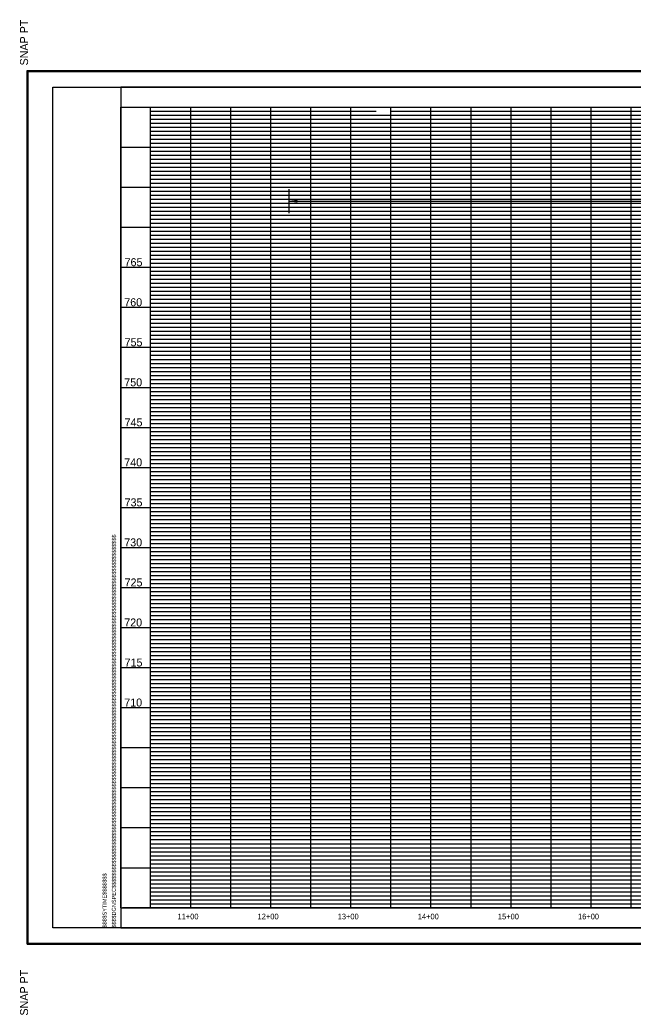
# Model space of a CAD drawing. Extents: x -273 to 1681765, y -325 to 521384.
# Drawn here: x 1680054 to 1680819, y 520141 to 521384 of the extents above; entities that cross this region are included whole.
import ezdxf

# ---------------------------------------------------------------- set-up
doc = ezdxf.new("R2010")
doc.units = 0
for name, color, linetype in [('DESIGN - PROFILE - Proposed Text', 7, 'Continuous'), ('DESIGN - SHEET - Corner Text', 7, 'Continuous'), ('DESIGN - SHEET - Light Grid', 7, 'Continuous'), ('DESIGN - SHEET - Linework', 7, 'Continuous'), ('DESIGN - SHEET - Plot Shape', 7, 'Continuous')]:
    doc.layers.add(name, color=color, linetype=linetype)

msp = doc.modelspace()

# ---------------------------------------------------------------- linework, layer by layer
at = {"layer": 'DESIGN - PROFILE - Proposed Text'}
for p, q in [((1680389.9, 521142.3), (1680389.9, 521172.3)), ((1680389.9, 521157.3), (1681439.9, 521157.3)), ((1680180, 520249.8), (1680180, 520249.8))]:
    msp.add_line(p, q, dxfattribs=at)
msp.add_lwpolyline([(1680389.9, 521157.3), (1680400, 521158.6), (1680398.7, 521157.3), (1680400, 521156)], close=True, dxfattribs=at)
msp.add_lwpolyline([(1680389.9, 521157.3), (1680400, 521158.6), (1680398.7, 521157.3), (1680400, 521156), (1680389.9, 521157.3)], dxfattribs=at)
at = {"layer": 'DESIGN - SHEET - Light Grid'}
for p, q in [((1680217.1, 521269.8), (1680498.7, 521269.8)), ((1680217.1, 521264.8), (1680517.1, 521264.8)), ((1680217.1, 521259.8), (1680517.1, 521259.8)), ((1680517.1, 521269.8), (1680867.1, 521269.8)), ((1680517.1, 521264.8), (1680867.1, 521264.8)), ((1680517.1, 521259.8), (1680867.1, 521259.8)), ((1680217.1, 521254.8), (1680517.1, 521254.8)), ((1680217.1, 521249.8), (1680517.1, 521249.8)), ((1680517.1, 521254.8), (1680867.1, 521254.8)), ((1680517.1, 521249.8), (1680867.1, 521249.8)), ((1680217.1, 521244.8), (1680517.1, 521244.8)), ((1680217.1, 521239.8), (1680517.1, 521239.8)), ((1680217.1, 521234.8), (1680517.1, 521234.8)), ((1680517.1, 521244.8), (1680867.1, 521244.8)), ((1680517.1, 521239.8), (1680867.1, 521239.8)), ((1680517.1, 521234.8), (1680867.1, 521234.8)), ((1680217.1, 521229.8), (1680517.1, 521229.8)), ((1680517.1, 521229.8), (1680867.1, 521229.8)), ((1680217.1, 521219.8), (1680517.1, 521219.8)), ((1680217.1, 521214.8), (1680517.1, 521214.8)), ((1680217.1, 521209.8), (1680517.1, 521209.8)), ((1680517.1, 521219.8), (1680867.1, 521219.8)), ((1680517.1, 521214.8), (1680867.1, 521214.8)), ((1680517.1, 521209.8), (1680867.1, 521209.8)), ((1680217.1, 521204.8), (1680517.1, 521204.8)), ((1680217.1, 521199.8), (1680517.1, 521199.8)), ((1680517.1, 521204.8), (1680867.1, 521204.8)), ((1680517.1, 521199.8), (1680867.1, 521199.8)), ((1680217.1, 521194.8), (1680517.1, 521194.8)), ((1680217.1, 521189.8), (1680517.1, 521189.8)), ((1680217.1, 521184.8), (1680517.1, 521184.8)), ((1680517.1, 521194.8), (1680867.1, 521194.8)), ((1680517.1, 521189.8), (1680867.1, 521189.8)), ((1680517.1, 521184.8), (1680867.1, 521184.8)), ((1680217.1, 521179.8), (1680517.1, 521179.8)), ((1680517.1, 521179.8), (1680867.1, 521179.8)), ((1680217.1, 521169.8), (1680517.1, 521169.8)), ((1680217.1, 521164.8), (1680517.1, 521164.8)), ((1680217.1, 521159.8), (1680517.1, 521159.8)), ((1680517.1, 521169.8), (1680867.1, 521169.8)), ((1680517.1, 521164.8), (1680867.1, 521164.8)), ((1680517.1, 521159.8), (1680867.1, 521159.8)), ((1680217.1, 521154.8), (1680517.1, 521154.8)), ((1680217.1, 521149.8), (1680517.1, 521149.8)), ((1680517.1, 521154.8), (1680867.1, 521154.8)), ((1680517.1, 521149.8), (1680867.1, 521149.8)), ((1680217.1, 521144.8), (1680517.1, 521144.8)), ((1680217.1, 521139.8), (1680517.1, 521139.8)), ((1680217.1, 521134.8), (1680517.1, 521134.8)), ((1680517.1, 521144.8), (1680867.1, 521144.8)), ((1680517.1, 521139.8), (1680867.1, 521139.8)), ((1680517.1, 521134.8), (1680867.1, 521134.8)), ((1680217.1, 521129.8), (1680517.1, 521129.8)), ((1680517.1, 521129.8), (1680867.1, 521129.8)), ((1680217.1, 521119.8), (1680517.1, 521119.8)), ((1680217.1, 521114.8), (1680517.1, 521114.8)), ((1680217.1, 521109.8), (1680517.1, 521109.8)), ((1680517.1, 521119.8), (1680867.1, 521119.8)), ((1680517.1, 521114.8), (1680867.1, 521114.8)), ((1680517.1, 521109.8), (1680867.1, 521109.8)), ((1680217.1, 521104.8), (1680517.1, 521104.8)), ((1680217.1, 521099.8), (1680517.1, 521099.8)), ((1680517.1, 521104.8), (1680867.1, 521104.8)), ((1680517.1, 521099.8), (1680867.1, 521099.8)), ((1680217.1, 521094.8), (1680517.1, 521094.8)), ((1680217.1, 521089.8), (1680517.1, 521089.8)), ((1680217.1, 521084.8), (1680517.1, 521084.8)), ((1680517.1, 521094.8), (1680867.1, 521094.8)), ((1680517.1, 521089.8), (1680867.1, 521089.8)), ((1680517.1, 521084.8), (1680867.1, 521084.8)), ((1680217.1, 521079.8), (1680517.1, 521079.8)), ((1680517.1, 521079.8), (1680867.1, 521079.8)), ((1680217.1, 521069.8), (1680517.1, 521069.8)), ((1680217.1, 521064.8), (1680517.1, 521064.8)), ((1680217.1, 521059.8), (1680517.1, 521059.8)), ((1680517.1, 521069.8), (1680867.1, 521069.8)), ((1680517.1, 521064.8), (1680867.1, 521064.8)), ((1680517.1, 521059.8), (1680867.1, 521059.8)), ((1680217.1, 521054.8), (1680517.1, 521054.8)), ((1680217.1, 521049.8), (1680517.1, 521049.8)), ((1680517.1, 521054.8), (1680867.1, 521054.8)), ((1680517.1, 521049.8), (1680867.1, 521049.8)), ((1680217.1, 521044.8), (1680517.1, 521044.8)), ((1680217.1, 521039.8), (1680517.1, 521039.8)), ((1680217.1, 521034.8), (1680517.1, 521034.8)), ((1680517.1, 521044.8), (1680867.1, 521044.8)), ((1680517.1, 521039.8), (1680867.1, 521039.8)), ((1680517.1, 521034.8), (1680867.1, 521034.8)), ((1680217.1, 521029.8), (1680517.1, 521029.8)), ((1680517.1, 521029.8), (1680867.1, 521029.8)), ((1680217.1, 521019.8), (1680517.1, 521019.8)), ((1680217.1, 521014.8), (1680517.1, 521014.8)), ((1680217.1, 521009.8), (1680517.1, 521009.8)), ((1680517.1, 521019.8), (1680867.1, 521019.8)), ((1680517.1, 521014.8), (1680867.1, 521014.8)), ((1680517.1, 521009.8), (1680867.1, 521009.8)), ((1680217.1, 521004.8), (1680517.1, 521004.8)), ((1680217.1, 520999.8), (1680517.1, 520999.8)), ((1680517.1, 521004.8), (1680867.1, 521004.8)), ((1680517.1, 520999.8), (1680867.1, 520999.8)), ((1680217.1, 520994.8), (1680517.1, 520994.8)), ((1680217.1, 520989.8), (1680517.1, 520989.8)), ((1680217.1, 520984.8), (1680517.1, 520984.8)), ((1680517.1, 520994.8), (1680867.1, 520994.8)), ((1680517.1, 520989.8), (1680867.1, 520989.8)), ((1680517.1, 520984.8), (1680867.1, 520984.8)), ((1680217.1, 520979.8), (1680517.1, 520979.8)), ((1680517.1, 520979.8), (1680867.1, 520979.8)), ((1680217.1, 520969.8), (1680517.1, 520969.8)), ((1680217.1, 520964.8), (1680517.1, 520964.8)), ((1680217.1, 520959.8), (1680517.1, 520959.8)), ((1680517.1, 520969.8), (1680867.1, 520969.8)), ((1680517.1, 520964.8), (1680867.1, 520964.8)), ((1680517.1, 520959.8), (1680867.1, 520959.8)), ((1680217.1, 520954.8), (1680517.1, 520954.8)), ((1680217.1, 520949.8), (1680517.1, 520949.8)), ((1680517.1, 520954.8), (1680867.1, 520954.8)), ((1680517.1, 520949.8), (1680867.1, 520949.8)), ((1680217.1, 520944.8), (1680517.1, 520944.8)), ((1680217.1, 520939.8), (1680517.1, 520939.8)), ((1680217.1, 520934.8), (1680517.1, 520934.8)), ((1680517.1, 520944.8), (1680867.1, 520944.8)), ((1680517.1, 520939.8), (1680867.1, 520939.8)), ((1680517.1, 520934.8), (1680867.1, 520934.8)), ((1680217.1, 520929.8), (1680517.1, 520929.8)), ((1680517.1, 520929.8), (1680867.1, 520929.8)), ((1680217.1, 520919.8), (1680517.1, 520919.8)), ((1680217.1, 520914.8), (1680517.1, 520914.8)), ((1680517.1, 520919.8), (1680867.1, 520919.8)), ((1680517.1, 520914.8), (1680867.1, 520914.8)), ((1680217.1, 520909.8), (1680517.1, 520909.8)), ((1680217.1, 520904.8), (1680517.1, 520904.8)), ((1680217.1, 520899.8), (1680517.1, 520899.8)), ((1680517.1, 520909.8), (1680867.1, 520909.8)), ((1680517.1, 520904.8), (1680867.1, 520904.8)), ((1680517.1, 520899.8), (1680867.1, 520899.8)), ((1680217.1, 520894.8), (1680517.1, 520894.8)), ((1680217.1, 520889.8), (1680517.1, 520889.8)), ((1680517.1, 520894.8), (1680867.1, 520894.8)), ((1680517.1, 520889.8), (1680867.1, 520889.8)), ((1680217.1, 520884.8), (1680517.1, 520884.8)), ((1680217.1, 520879.8), (1680517.1, 520879.8)), ((1680517.1, 520884.8), (1680867.1, 520884.8)), ((1680517.1, 520879.8), (1680867.1, 520879.8)), ((1680217.1, 520869.8), (1680517.1, 520869.8)), ((1680217.1, 520864.8), (1680517.1, 520864.8)), ((1680517.1, 520869.8), (1680867.1, 520869.8)), ((1680517.1, 520864.8), (1680867.1, 520864.8)), ((1680217.1, 520859.8), (1680517.1, 520859.8)), ((1680217.1, 520854.8), (1680517.1, 520854.8)), ((1680217.1, 520849.8), (1680517.1, 520849.8)), ((1680517.1, 520859.8), (1680867.1, 520859.8)), ((1680517.1, 520854.8), (1680867.1, 520854.8)), ((1680517.1, 520849.8), (1680867.1, 520849.8)), ((1680217.1, 520844.8), (1680517.1, 520844.8)), ((1680217.1, 520839.8), (1680517.1, 520839.8)), ((1680517.1, 520844.8), (1680867.1, 520844.8)), ((1680517.1, 520839.8), (1680867.1, 520839.8)), ((1680217.1, 520834.8), (1680517.1, 520834.8)), ((1680217.1, 520829.8), (1680517.1, 520829.8)), ((1680517.1, 520834.8), (1680867.1, 520834.8)), ((1680517.1, 520829.8), (1680867.1, 520829.8)), ((1680217.1, 520819.8), (1680517.1, 520819.8)), ((1680217.1, 520814.8), (1680517.1, 520814.8)), ((1680517.1, 520819.8), (1680867.1, 520819.8)), ((1680517.1, 520814.8), (1680867.1, 520814.8)), ((1680217.1, 520809.8), (1680517.1, 520809.8)), ((1680217.1, 520804.8), (1680517.1, 520804.8)), ((1680217.1, 520799.8), (1680517.1, 520799.8)), ((1680517.1, 520809.8), (1680867.1, 520809.8)), ((1680517.1, 520804.8), (1680867.1, 520804.8)), ((1680517.1, 520799.8), (1680867.1, 520799.8)), ((1680217.1, 520794.8), (1680517.1, 520794.8)), ((1680217.1, 520789.8), (1680517.1, 520789.8)), ((1680517.1, 520794.8), (1680867.1, 520794.8)), ((1680517.1, 520789.8), (1680867.1, 520789.8)), ((1680217.1, 520784.8), (1680517.1, 520784.8)), ((1680217.1, 520779.8), (1680517.1, 520779.8)), ((1680517.1, 520784.8), (1680867.1, 520784.8)), ((1680517.1, 520779.8), (1680867.1, 520779.8)), ((1680217.1, 520769.8), (1680517.1, 520769.8)), ((1680217.1, 520764.8), (1680517.1, 520764.8)), ((1680517.1, 520769.8), (1680867.1, 520769.8)), ((1680517.1, 520764.8), (1680867.1, 520764.8)), ((1680217.1, 520759.8), (1680517.1, 520759.8)), ((1680217.1, 520754.8), (1680517.1, 520754.8)), ((1680217.1, 520749.8), (1680517.1, 520749.8)), ((1680517.1, 520759.8), (1680867.1, 520759.8)), ((1680517.1, 520754.8), (1680867.1, 520754.8)), ((1680517.1, 520749.8), (1680867.1, 520749.8)), ((1680217.1, 520744.8), (1680517.1, 520744.8)), ((1680217.1, 520739.8), (1680517.1, 520739.8)), ((1680517.1, 520744.8), (1680867.1, 520744.8)), ((1680517.1, 520739.8), (1680867.1, 520739.8)), ((1680217.1, 520734.8), (1680517.1, 520734.8)), ((1680217.1, 520729.8), (1680517.1, 520729.8)), ((1680517.1, 520734.8), (1680867.1, 520734.8)), ((1680517.1, 520729.8), (1680867.1, 520729.8)), ((1680217.1, 520719.8), (1680517.1, 520719.8)), ((1680217.1, 520714.8), (1680517.1, 520714.8)), ((1680517.1, 520719.8), (1680867.1, 520719.8)), ((1680517.1, 520714.8), (1680867.1, 520714.8)), ((1680217.1, 520709.8), (1680517.1, 520709.8)), ((1680217.1, 520704.8), (1680517.1, 520704.8)), ((1680217.1, 520699.8), (1680517.1, 520699.8)), ((1680517.1, 520709.8), (1680867.1, 520709.8)), ((1680517.1, 520704.8), (1680867.1, 520704.8)), ((1680517.1, 520699.8), (1680867.1, 520699.8)), ((1680217.1, 520694.8), (1680517.1, 520694.8)), ((1680217.1, 520689.8), (1680517.1, 520689.8)), ((1680517.1, 520694.8), (1680867.1, 520694.8)), ((1680517.1, 520689.8), (1680867.1, 520689.8)), ((1680217.1, 520684.8), (1680517.1, 520684.8)), ((1680217.1, 520679.8), (1680517.1, 520679.8)), ((1680517.1, 520684.8), (1680867.1, 520684.8)), ((1680517.1, 520679.8), (1680867.1, 520679.8)), ((1680217.1, 520669.8), (1680517.1, 520669.8)), ((1680217.1, 520664.8), (1680517.1, 520664.8)), ((1680517.1, 520669.8), (1680867.1, 520669.8)), ((1680517.1, 520664.8), (1680867.1, 520664.8)), ((1680217.1, 520659.8), (1680517.1, 520659.8)), ((1680217.1, 520654.8), (1680517.1, 520654.8)), ((1680217.1, 520649.8), (1680517.1, 520649.8)), ((1680517.1, 520659.8), (1680867.1, 520659.8)), ((1680517.1, 520654.8), (1680867.1, 520654.8)), ((1680517.1, 520649.8), (1680867.1, 520649.8)), ((1680217.1, 520644.8), (1680517.1, 520644.8)), ((1680217.1, 520639.8), (1680517.1, 520639.8)), ((1680517.1, 520644.8), (1680867.1, 520644.8)), ((1680517.1, 520639.8), (1680867.1, 520639.8)), ((1680217.1, 520634.8), (1680517.1, 520634.8)), ((1680217.1, 520629.8), (1680517.1, 520629.8)), ((1680517.1, 520634.8), (1680867.1, 520634.8)), ((1680517.1, 520629.8), (1680867.1, 520629.8)), ((1680217.1, 520619.8), (1680517.1, 520619.8)), ((1680217.1, 520614.8), (1680517.1, 520614.8)), ((1680517.1, 520619.8), (1680867.1, 520619.8)), ((1680517.1, 520614.8), (1680867.1, 520614.8)), ((1680217.1, 520609.8), (1680517.1, 520609.8)), ((1680217.1, 520604.8), (1680517.1, 520604.8)), ((1680217.1, 520599.8), (1680517.1, 520599.8)), ((1680517.1, 520609.8), (1680867.1, 520609.8)), ((1680517.1, 520604.8), (1680867.1, 520604.8)), ((1680517.1, 520599.8), (1680867.1, 520599.8)), ((1680217.1, 520594.8), (1680517.1, 520594.8)), ((1680217.1, 520589.8), (1680517.1, 520589.8)), ((1680517.1, 520594.8), (1680867.1, 520594.8)), ((1680517.1, 520589.8), (1680867.1, 520589.8)), ((1680217.1, 520584.8), (1680517.1, 520584.8)), ((1680217.1, 520579.8), (1680517.1, 520579.8)), ((1680517.1, 520584.8), (1680867.1, 520584.8)), ((1680517.1, 520579.8), (1680867.1, 520579.8)), ((1680217.1, 520569.8), (1680517.1, 520569.8)), ((1680217.1, 520564.8), (1680517.1, 520564.8)), ((1680517.1, 520569.8), (1680867.1, 520569.8)), ((1680517.1, 520564.8), (1680867.1, 520564.8)), ((1680217.1, 520559.8), (1680517.1, 520559.8)), ((1680217.1, 520554.8), (1680517.1, 520554.8)), ((1680217.1, 520549.8), (1680517.1, 520549.8)), ((1680517.1, 520559.8), (1680867.1, 520559.8)), ((1680517.1, 520554.8), (1680867.1, 520554.8)), ((1680517.1, 520549.8), (1680867.1, 520549.8)), ((1680217.1, 520544.8), (1680517.1, 520544.8)), ((1680217.1, 520539.8), (1680517.1, 520539.8)), ((1680517.1, 520544.8), (1680867.1, 520544.8)), ((1680517.1, 520539.8), (1680867.1, 520539.8)), ((1680217.1, 520534.8), (1680517.1, 520534.8)), ((1680217.1, 520529.8), (1680517.1, 520529.8)), ((1680517.1, 520534.8), (1680867.1, 520534.8)), ((1680517.1, 520529.8), (1680867.1, 520529.8)), ((1680217.1, 520519.8), (1680517.1, 520519.8)), ((1680217.1, 520514.8), (1680517.1, 520514.8)), ((1680517.1, 520519.8), (1680867.1, 520519.8)), ((1680517.1, 520514.8), (1680867.1, 520514.8)), ((1680217.1, 520509.8), (1680517.1, 520509.8)), ((1680217.1, 520504.8), (1680517.1, 520504.8)), ((1680217.1, 520499.8), (1680517.1, 520499.8)), ((1680517.1, 520509.8), (1680867.1, 520509.8)), ((1680517.1, 520504.8), (1680867.1, 520504.8)), ((1680517.1, 520499.8), (1680867.1, 520499.8)), ((1680217.1, 520494.8), (1680517.1, 520494.8)), ((1680217.1, 520489.8), (1680517.1, 520489.8)), ((1680517.1, 520494.8), (1680867.1, 520494.8)), ((1680517.1, 520489.8), (1680867.1, 520489.8)), ((1680217.1, 520484.8), (1680517.1, 520484.8)), ((1680217.1, 520479.8), (1680517.1, 520479.8)), ((1680517.1, 520484.8), (1680867.1, 520484.8)), ((1680517.1, 520479.8), (1680867.1, 520479.8)), ((1680217.1, 520469.8), (1680517.1, 520469.8)), ((1680217.1, 520464.8), (1680517.1, 520464.8)), ((1680517.1, 520469.8), (1680867.1, 520469.8)), ((1680517.1, 520464.8), (1680867.1, 520464.8)), ((1680217.1, 520459.8), (1680517.1, 520459.8)), ((1680217.1, 520454.8), (1680517.1, 520454.8)), ((1680517.1, 520459.8), (1680867.1, 520459.8)), ((1680517.1, 520454.8), (1680867.1, 520454.8)), ((1680217.1, 520449.8), (1680517.1, 520449.8)), ((1680217.1, 520444.8), (1680517.1, 520444.8)), ((1680217.1, 520439.8), (1680517.1, 520439.8)), ((1680517.1, 520449.8), (1680867.1, 520449.8)), ((1680517.1, 520444.8), (1680867.1, 520444.8)), ((1680517.1, 520439.8), (1680867.1, 520439.8)), ((1680217.1, 520434.8), (1680517.1, 520434.8)), ((1680217.1, 520429.8), (1680517.1, 520429.8)), ((1680517.1, 520434.8), (1680867.1, 520434.8)), ((1680517.1, 520429.8), (1680867.1, 520429.8)), ((1680217.1, 520419.8), (1680517.1, 520419.8)), ((1680217.1, 520414.8), (1680517.1, 520414.8)), ((1680517.1, 520419.8), (1680867.1, 520419.8)), ((1680517.1, 520414.8), (1680867.1, 520414.8)), ((1680217.1, 520409.8), (1680517.1, 520409.8)), ((1680217.1, 520404.8), (1680517.1, 520404.8)), ((1680517.1, 520409.8), (1680867.1, 520409.8)), ((1680517.1, 520404.8), (1680867.1, 520404.8)), ((1680217.1, 520399.8), (1680517.1, 520399.8)), ((1680217.1, 520394.8), (1680517.1, 520394.8)), ((1680217.1, 520389.8), (1680517.1, 520389.8)), ((1680517.1, 520399.8), (1680867.1, 520399.8)), ((1680517.1, 520394.8), (1680867.1, 520394.8)), ((1680517.1, 520389.8), (1680867.1, 520389.8)), ((1680217.1, 520384.8), (1680517.1, 520384.8)), ((1680217.1, 520379.8), (1680517.1, 520379.8)), ((1680517.1, 520384.8), (1680867.1, 520384.8)), ((1680517.1, 520379.8), (1680867.1, 520379.8)), ((1680217.1, 520369.8), (1680517.1, 520369.8)), ((1680217.1, 520364.8), (1680517.1, 520364.8)), ((1680517.1, 520369.8), (1680867.1, 520369.8)), ((1680517.1, 520364.8), (1680867.1, 520364.8)), ((1680217.1, 520359.8), (1680517.1, 520359.8)), ((1680217.1, 520354.8), (1680517.1, 520354.8)), ((1680517.1, 520359.8), (1680867.1, 520359.8)), ((1680517.1, 520354.8), (1680867.1, 520354.8)), ((1680217.1, 520349.8), (1680517.1, 520349.8)), ((1680217.1, 520344.8), (1680517.1, 520344.8)), ((1680217.1, 520339.8), (1680517.1, 520339.8)), ((1680517.1, 520349.8), (1680867.1, 520349.8)), ((1680517.1, 520344.8), (1680867.1, 520344.8)), ((1680517.1, 520339.8), (1680867.1, 520339.8)), ((1680217.1, 520334.8), (1680517.1, 520334.8)), ((1680217.1, 520329.8), (1680517.1, 520329.8)), ((1680517.1, 520334.8), (1680867.1, 520334.8)), ((1680517.1, 520329.8), (1680867.1, 520329.8)), ((1680217.1, 520319.8), (1680517.1, 520319.8)), ((1680217.1, 520314.8), (1680517.1, 520314.8)), ((1680517.1, 520319.8), (1680867.1, 520319.8)), ((1680517.1, 520314.8), (1680867.1, 520314.8)), ((1680217.1, 520309.8), (1680517.1, 520309.8)), ((1680217.1, 520304.8), (1680517.1, 520304.8)), ((1680517.1, 520309.8), (1680867.1, 520309.8)), ((1680517.1, 520304.8), (1680867.1, 520304.8)), ((1680217.1, 520299.8), (1680517.1, 520299.8)), ((1680217.1, 520294.8), (1680517.1, 520294.8)), ((1680217.1, 520289.8), (1680517.1, 520289.8)), ((1680517.1, 520299.8), (1680867.1, 520299.8)), ((1680517.1, 520294.8), (1680867.1, 520294.8)), ((1680517.1, 520289.8), (1680867.1, 520289.8)), ((1680217.1, 520284.8), (1680517.1, 520284.8)), ((1680217.1, 520279.8), (1680517.1, 520279.8)), ((1680517.1, 520284.8), (1680867.1, 520284.8)), ((1680517.1, 520279.8), (1680867.1, 520279.8))]:
    msp.add_line(p, q, dxfattribs=at)
at = {"layer": 'DESIGN - SHEET - Linework'}
for p, q in [((1680063.1, 520229.1), (1680063.1, 521320.5)), ((1680063.1, 521320.5), (1681765.1, 521320.5)), ((1680182.1, 521274.8), (1681554.2, 521274.8)), ((1680217.1, 520274.8), (1680217.1, 521274.8)), ((1680267.1, 520274.8), (1680267.1, 521274.8)), ((1680317.1, 520274.8), (1680317.1, 521274.8)), ((1680367.1, 520274.8), (1680367.1, 521274.8)), ((1680417.1, 520274.8), (1680417.1, 521274.8)), ((1680467.1, 520274.8), (1680467.1, 521274.8)), ((1680517.1, 520274.8), (1680517.1, 521274.8)), ((1680567.1, 520274.8), (1680567.1, 521274.8)), ((1680617.1, 520274.8), (1680617.1, 521274.8)), ((1680667.1, 520274.8), (1680667.1, 521274.8)), ((1680717.1, 520274.8), (1680717.1, 521274.8)), ((1680767.1, 520274.8), (1680767.1, 521274.8)), ((1680817.1, 520274.8), (1680817.1, 521274.8)), ((1680180, 521224.8), (1681554.2, 521224.8)), ((1680180, 521174.8), (1681554.2, 521174.8)), ((1680180, 521124.8), (1681554.2, 521124.8)), ((1680180, 521074.8), (1681554.2, 521074.8)), ((1680180, 521024.8), (1681554.2, 521024.8)), ((1680180, 520974.8), (1681554.2, 520974.8)), ((1680180, 520924.8), (1681554.2, 520924.8)), ((1680180, 520874.8), (1681554.2, 520874.8)), ((1680180, 520824.8), (1681554.2, 520824.8)), ((1680180, 520774.8), (1681554.2, 520774.8)), ((1680180, 520724.8), (1681554.2, 520724.8)), ((1680180, 520674.8), (1681554.2, 520674.8)), ((1680180, 520624.8), (1681554.2, 520624.8)), ((1680180, 520574.8), (1681554.2, 520574.8)), ((1680180, 520524.8), (1681554.2, 520524.8)), ((1680180, 520474.8), (1681554.2, 520474.8)), ((1680180, 520424.8), (1681554.2, 520424.8)), ((1680180, 520374.8), (1681554.2, 520374.8)), ((1680180, 520324.8), (1681554.2, 520324.8)), ((1680180, 520274.8), (1681554.2, 520274.8)), ((1680063.1, 520229.1), (1681765.1, 520229.1))]:
    msp.add_line(p, q, dxfattribs=at)
for points in [[(1680180, 521299.8), (1680180, 520249.8), (1681754.2, 520249.8), (1681754.2, 521299.8), (1680180, 521299.8)], [(1680180, 520274.8), (1680180, 521274.8), (1681554.2, 521274.8), (1681554.2, 520274.8), (1680182.1, 520274.8)]]:
    msp.add_lwpolyline(points, dxfattribs=at)
at = {"layer": 'DESIGN - SHEET - Plot Shape'}
for points in [[(1680064.1, 521319.5), (1681764.1, 521319.5), (1681764.1, 520230.1), (1680064.1, 520230.1)], [(1680095, 521299.8), (1681754.2, 521299.8), (1681754.2, 520249.8), (1680095, 520249.8)]]:
    msp.add_lwpolyline(points, close=True, dxfattribs=at)

# ---------------------------------------------------------------- texts
at = {"layer": 'DESIGN - SHEET - Corner Text'}
for s, height, p in [('  SNAP PT', 10, (1680064.1, 521319.5)), ('$$$$DGNSPEC$$$$$$$$$$$$$$$$$$$$$$$$$$$$$$$$$$$$$$$$$$$$$$$$$$$$$$$$$$$$$$$$$$$$$$$$$$$$$$$$$$$$$$$$$$$$$$$$$$$$$$$$$$$$$$$$$$$', 5.0001, (1680173.7, 520249.8)), ('$$$$SYTIME$$$$$$$', 5, (1680162.1, 520249.8)), ('SNAP PT  ', 10, (1680064.1, 520140.1))]:
    msp.add_text(s, height=height, rotation=90, dxfattribs=at).set_placement(p)
for s, height, p in [('765', 10, (1680184.6, 521076.1)), ('760', 10, (1680184.2, 521026.1)), ('755', 10, (1680184.6, 520976.1)), ('750', 10, (1680184.2, 520926.1)), ('745', 10, (1680184.6, 520876.1)), ('740', 10, (1680184.2, 520826.1)), ('735', 10, (1680184.6, 520776.1)), ('730', 10, (1680184.2, 520726.1)), ('725', 10, (1680184.6, 520676.1)), ('720', 10, (1680184.2, 520626.1)), ('715', 10, (1680184.6, 520576.1)), ('710', 10, (1680184.2, 520526.1)), ('11+00', 7, (1680250.6, 520260.3)), ('12+00', 7, (1680350.6, 520260.3)), ('13+00', 7, (1680450.6, 520260.3)), ('14+00', 7, (1680550.6, 520260.3)), ('15+00', 7, (1680650.6, 520260.3)), ('16+00', 7, (1680750.6, 520260.3))]:
    msp.add_text(s, height=height, dxfattribs=at).set_placement(p)

doc.saveas('drawing.dxf')
